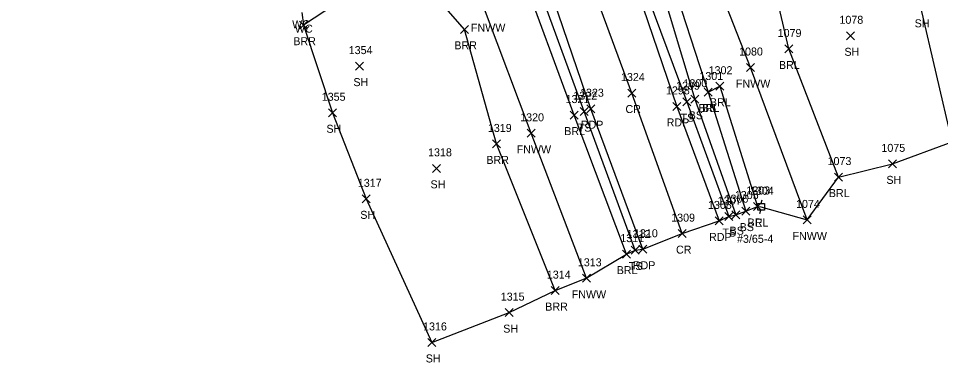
# Model space of a CAD drawing. Extents: x 1443590 to 1445966, y 578314 to 580556.
# Drawn here: x 1445262.8 to 1445493.3, y 578313.7 to 578399.7 of the extents above; entities that cross this region are included whole.
import ezdxf

# ---------------------------------------------------------------- set-up
doc = ezdxf.new("R2010")
doc.units = 0
for name, color, linetype in [('L_A', 7, 'Continuous'), ('L_I', 7, 'Continuous'), ('L_TIC', 7, 'Continuous'), ('LABL', 7, 'Continuous'), ('LELB', 7, 'Continuous'), ('LFNC', 7, 'Continuous'), ('LSOGP', 7, 'Continuous'), ('P_A', 7, 'Continuous'), ('P_I', 7, 'Continuous'), ('P_TIC', 7, 'Continuous'), ('PET', 7, 'Continuous'), ('PRC', 7, 'Continuous'), ('U_A', 7, 'Continuous'), ('U_C', 7, 'Continuous'), ('U_I', 7, 'Continuous'), ('UEPT', 7, 'Continuous')]:
    doc.layers.add(name, color=color, linetype=linetype)

msp = doc.modelspace()

# ---------------------------------------------------------------- linework, layer by layer
at = {"layer": 'L_TIC'}
for points in [[(1445333.02, 578397.02), (1445335.02, 578399.02)], [(1445335.02, 578397.02), (1445333.02, 578399.02)], [(1445373.28, 578395.98), (1445375.28, 578397.98)], [(1445375.28, 578395.98), (1445373.28, 578397.98)], [(1445469.81, 578394.37), (1445471.81, 578396.37)], [(1445471.81, 578394.37), (1445469.81, 578396.37)], [(1445454.38, 578391.07), (1445456.38, 578393.07)], [(1445456.38, 578391.07), (1445454.38, 578393.07)], [(1445347.05, 578386.79), (1445349.05, 578388.79)], [(1445349.05, 578386.79), (1445347.05, 578388.79)], [(1445444.8, 578386.44), (1445446.8, 578388.44)], [(1445446.8, 578386.44), (1445444.8, 578388.44)], [(1445437.11, 578381.76), (1445439.11, 578383.76)], [(1445439.11, 578381.76), (1445437.11, 578383.76)], [(1445430.91, 578378.51), (1445432.91, 578380.51)], [(1445432.91, 578378.51), (1445430.91, 578380.51)], [(1445434.24, 578380.31), (1445436.24, 578382.31)], [(1445436.24, 578380.31), (1445434.24, 578382.31)], [(1445434.24, 578380.31), (1445436.24, 578382.31)], [(1445436.24, 578380.31), (1445434.24, 578382.31)], [(1445428.91, 578377.9), (1445430.91, 578379.9)], [(1445430.91, 578377.9), (1445428.91, 578379.9)], [(1445340.32, 578375.13), (1445342.32, 578377.13)], [(1445342.32, 578375.13), (1445340.32, 578377.13)], [(1445400.7, 578374.55), (1445402.7, 578376.55)], [(1445402.7, 578374.55), (1445400.7, 578376.55)], [(1445403.21, 578375.42), (1445405.21, 578377.42)], [(1445405.21, 578375.42), (1445403.21, 578377.42)], [(1445390, 578369.99), (1445392, 578371.99)], [(1445392, 578369.99), (1445390, 578371.99)], [(1445381.28, 578367.34), (1445383.28, 578369.34)], [(1445383.28, 578367.34), (1445381.28, 578369.34)], [(1445480.3, 578362.36), (1445482.3, 578364.36)], [(1445482.3, 578362.36), (1445480.3, 578364.36)], [(1445366.33, 578361.24), (1445368.33, 578363.24)], [(1445368.33, 578361.24), (1445366.33, 578363.24)], [(1445466.84, 578359.06), (1445468.84, 578361.06)], [(1445468.84, 578359.06), (1445466.84, 578361.06)], [(1445348.76, 578353.62), (1445350.76, 578355.62)], [(1445350.76, 578353.62), (1445348.76, 578355.62)], [(1445446.54, 578351.71), (1445448.54, 578353.71)], [(1445448.54, 578351.71), (1445446.54, 578353.71)], [(1445439.4, 578349.18), (1445441.4, 578351.18)], [(1445441.4, 578349.18), (1445439.4, 578351.18)], [(1445441.14, 578349.66), (1445443.14, 578351.66)], [(1445443.14, 578349.66), (1445441.14, 578351.66)], [(1445443.66, 578350.56), (1445445.66, 578352.56)], [(1445445.66, 578350.56), (1445443.66, 578352.56)], [(1445458.96, 578348.35), (1445460.96, 578350.35)], [(1445460.96, 578348.35), (1445458.96, 578350.35)], [(1445413.81, 578339.8), (1445415.81, 578341.8)], [(1445415.81, 578339.8), (1445413.81, 578341.8)], [(1445415.98, 578340.83), (1445417.98, 578342.83)], [(1445417.98, 578340.83), (1445415.98, 578342.83)], [(1445403.77, 578333.76), (1445405.77, 578335.76)], [(1445405.77, 578333.76), (1445403.77, 578335.76)], [(1445396.01, 578330.68), (1445398.01, 578332.68)], [(1445398.01, 578330.68), (1445396.01, 578332.68)], [(1445384.5, 578325.18), (1445386.5, 578327.18)], [(1445386.5, 578325.18), (1445384.5, 578327.18)], [(1445365.13, 578317.73), (1445367.13, 578319.73)], [(1445367.13, 578317.73), (1445365.13, 578319.73)]]:
    msp.add_lwpolyline(points, dxfattribs=at)
at = {"layer": 'LABL'}
for points in [[(1445467.84, 578360.06), (1445455.38, 578392.07), (1445446.82, 578428.87), (1445442.38, 578441.48), (1445436.55, 578457.59), (1445425.34, 578488.87), (1445418.21, 578516.65), (1445402.21, 578560.94), (1445385.83, 578595.27), (1445371.99, 578640.68), (1445356.66, 578684.35), (1445342.86, 578722.22), (1445331.82, 578758.2), (1445312.95, 578811.34), (1445309.58, 578818.49), (1445306.72, 578822.66), (1445303.45, 578826.18), (1445294.95, 578830.16), (1445285.99, 578855.57), (1445278.07, 578895.34), (1445273.01, 578922.07), (1445267.74, 578942.65), (1445247.28, 578957.13)], [(1445292.63, 578789.9), (1445288, 578780.72), (1445303.45, 578740.92), (1445320.45, 578696.23), (1445336.45, 578651.8), (1445353.16, 578609.77), (1445368.17, 578573), (1445383.72, 578526.34), (1445398.46, 578486.57), (1445412.31, 578451.09), (1445415.12, 578445.83), (1445420.11, 578428.88), (1445425.31, 578411.87), (1445435.24, 578381.31), (1445438.11, 578382.76), (1445447.54, 578352.71)], [(1445414.81, 578340.8), (1445401.7, 578375.55), (1445388.17, 578412.4), (1445382.57, 578425.95), (1445377.8, 578432.04), (1445377.55, 578433.04), (1445376.34, 578435.51), (1445372.5, 578441.21), (1445366.97, 578466.65), (1445351.62, 578511.32), (1445336.85, 578548.71)], [(1445397.01, 578331.68), (1445382.28, 578368.34), (1445374.28, 578396.98), (1445358.31, 578415.37), (1445344.45, 578404.9), (1445334.02, 578398.02)]]:
    msp.add_lwpolyline(points, dxfattribs=at)
at = {"layer": 'LELB'}
for points in [[(1445222.69, 578937.93), (1445234.28, 578911.39), (1445254.78, 578861.13), (1445268.94, 578819.8), (1445281.41, 578785.26), (1445283.41, 578779.74), (1445299.6, 578739.58), (1445316.15, 578694.47), (1445332.79, 578650.27), (1445347.4, 578607.95), (1445361.62, 578570.36), (1445377.25, 578524), (1445391.22, 578483.59), (1445406.36, 578442.9), (1445418.34, 578410.04), (1445429.91, 578378.9), (1445440.4, 578350.18)], [(1445336.45, 578651.8), (1445350.45, 578608.68), (1445364.47, 578571.58), (1445379.66, 578524.91), (1445393.71, 578484.47), (1445409.17, 578449.94), (1445411.12, 578445.67), (1445411.54, 578444.09), (1445413.6, 578439.47), (1445415.72, 578428.29), (1445422.38, 578411.18), (1445431.91, 578379.51), (1445442.14, 578350.66)], [(1445416.98, 578341.83), (1445404.21, 578376.42), (1445390.71, 578413.34), (1445383.61, 578436.1), (1445371.7, 578468.44), (1445355.7, 578512.19), (1445341.33, 578550.44)], [(1445435.24, 578381.31), (1445444.66, 578351.56)]]:
    msp.add_lwpolyline(points, dxfattribs=at)
at = {"layer": 'LFNC'}
for points in [[(1445459.96, 578349.35), (1445445.8, 578387.44), (1445435.66, 578413.46), (1445430.43, 578428.44), (1445420.82, 578457.49), (1445411.95, 578480.76), (1445399.21, 578511.56), (1445382.81, 578556.03), (1445370.45, 578591.65), (1445354.37, 578635.55), (1445339.12, 578673.28), (1445323.48, 578719.9), (1445315.49, 578748.71)], [(1445404.77, 578334.76), (1445391, 578370.99), (1445379.57, 578401.39), (1445375.71, 578416.07)]]:
    msp.add_lwpolyline(points, dxfattribs=at)
at = {"layer": 'LSOGP'}
msp.add_lwpolyline([(1445333.6, 578401.15), (1445334.02, 578398.03), (1445341.32, 578376.13), (1445349.76, 578354.62), (1445366.13, 578318.74), (1445385.5, 578326.19), (1445397.01, 578331.68), (1445404.76, 578334.77), (1445414.81, 578340.8), (1445416.98, 578341.83), (1445418.89, 578342.02), (1445428.76, 578345.93), (1445437.94, 578349.11), (1445440.4, 578350.18), (1445442.14, 578350.66), (1445444.66, 578351.57), (1445447.54, 578352.71), (1445448.43, 578352.64), (1445459.96, 578349.35), (1445467.83, 578360.07), (1445481.3, 578363.36), (1445496.19, 578368.86), (1445488.35, 578402.49)], dxfattribs=at)
at = {"layer": 'P_TIC'}
for points in [[(1445415.12, 578380.06), (1445417.12, 578382.06)], [(1445417.12, 578380.06), (1445415.12, 578382.06)], [(1445426.35, 578376.72), (1445428.35, 578378.72)], [(1445428.35, 578376.72), (1445426.35, 578378.72)], [(1445404.88, 578376.14), (1445406.88, 578378.14)], [(1445406.88, 578376.14), (1445404.88, 578378.14)], [(1445436.94, 578348.1), (1445438.94, 578350.1)], [(1445438.94, 578348.1), (1445436.94, 578350.1)], [(1445427.76, 578344.92), (1445429.76, 578346.92)], [(1445429.76, 578344.92), (1445427.76, 578346.92)], [(1445417.89, 578341.02), (1445419.89, 578343.02)], [(1445419.89, 578341.02), (1445417.89, 578343.02)]]:
    msp.add_lwpolyline(points, dxfattribs=at)
at = {"layer": 'PET'}
for points in [[(1445418.89, 578342.02), (1445405.88, 578377.14), (1445393.26, 578414.23), (1445384.94, 578436.64), (1445373.41, 578468.96), (1445357.56, 578512.83), (1445344.62, 578550.03), (1445330.99, 578586.22), (1445323.64, 578606.66), (1445310.56, 578643.56), (1445297.05, 578680.63), (1445286.07, 578712.45), (1445276.51, 578732.61), (1445268.43, 578753.25), (1445256.91, 578785.04), (1445249.61, 578806.41), (1445230.56, 578857.31), (1445217.97, 578888.99), (1445200.05, 578931.7), (1445199.72, 578935.44), (1445193.89, 578943.66), (1445183.72, 578968.31), (1445171.41, 579000.64)], [(1445204.47, 578977.72), (1445211.07, 578960.69), (1445220.5, 578936.98), (1445230.76, 578910.15), (1445251.08, 578859.52), (1445265.4, 578819.79), (1445279.28, 578781.46), (1445295.62, 578738.27), (1445312.78, 578693.03), (1445329.09, 578649.05), (1445344.77, 578606.81), (1445359.16, 578569.06), (1445375.47, 578523.38), (1445389.92, 578483.27), (1445404.56, 578441.9), (1445416.57, 578409.56), (1445427.35, 578377.72), (1445437.94, 578349.1)]]:
    msp.add_lwpolyline(points, dxfattribs=at)
at = {"layer": 'PRC'}
msp.add_lwpolyline([(1445428.76, 578345.92), (1445416.12, 578381.06), (1445402.82, 578417.2), (1445394.53, 578440.03), (1445382.79, 578472.56), (1445367.55, 578515.78), (1445354.3, 578552.77), (1445340.07, 578591.68), (1445332.93, 578610.75), (1445320.05, 578646.79), (1445306.48, 578683.94), (1445294.78, 578715.83), (1445285.68, 578740.23), (1445278.69, 578759.19), (1445266.72, 578790.29), (1445259.42, 578810.95), (1445240.14, 578861.33), (1445228.56, 578891.21), (1445209.9, 578937.12), (1445195.27, 578973.7), (1445179.73, 579007.4), (1445167.09, 579032.9), (1445157.85, 579050.89), (1445142.74, 579080.19)], dxfattribs=at)
at = {"layer": 'UEPT'}
for p, q in [((1445447.6, 578351.8), (1445447.6, 578353.47)), ((1445447.6, 578353.47), (1445449.27, 578353.47)), ((1445448.6, 578354.3), (1445448.43, 578353.47)), ((1445449.27, 578353.47), (1445449.27, 578351.8)), ((1445449.27, 578351.8), (1445447.6, 578351.8)), ((1445448.18, 578350.97), (1445448.43, 578351.8)), ((1445448.43, 578352.63), (1445448.43, 578352.63))]:
    msp.add_line(p, q, dxfattribs=at)

# ---------------------------------------------------------------- texts
at = {"layer": 'L_A'}
for s, p in [('WC', (1445331.21, 578397.26)), ('SH', (1445486.84, 578397.49)), ('WC', (1445331.91, 578396.15)), ('FNWW', (1445375.91, 578396.39)), ('BRR', (1445331.51, 578393.02)), ('BRR', (1445371.77, 578391.98)), ('SH', (1445469.3, 578390.37)), ('BRL', (1445452.92, 578387.07)), ('SH', (1445346.54, 578382.79)), ('FNWW', (1445442.15, 578382.44)), ('BRL', (1445432.78, 578376.31)), ('BS', (1445433.68, 578376.31)), ('BRL', (1445435.65, 578377.76)), ('TS', (1445428.32, 578373.9)), ('BS', (1445430.35, 578374.51)), ('SH', (1445339.8, 578371.13)), ('BRL', (1445399.24, 578370.55)), ('TS', (1445402.62, 578371.42)), ('FNWW', (1445387.35, 578365.99)), ('BRR', (1445379.77, 578363.34)), ('SH', (1445479.78, 578358.36)), ('SH', (1445365.81, 578357.24)), ('BRL', (1445465.38, 578355.06)), ('SH', (1445348.25, 578349.62)), ('BS', (1445443.1, 578346.56)), ('BRL', (1445445.08, 578347.71)), ('TS', (1445438.81, 578345.18)), ('BS', (1445440.58, 578345.66)), ('FNWW', (1445456.31, 578344.35)), ('BRL', (1445412.36, 578335.8)), ('TS', (1445415.39, 578336.83)), ('FNWW', (1445401.11, 578329.76)), ('BRR', (1445394.5, 578326.68)), ('SH', (1445383.99, 578321.18)), ('SH', (1445364.62, 578313.73))]:
    msp.add_text(s, height=2, dxfattribs=at).set_placement(p)
at = {"layer": 'L_I'}
for s, p in [('1078', (1445468.04, 578398.37)), ('1079', (1445452.6, 578395.07)), ('1354', (1445345.36, 578390.79)), ('1080', (1445442.95, 578390.44)), ('1302', (1445435.34, 578385.76)), ('1301', (1445433.03, 578384.31)), ('1301', (1445433.03, 578384.31)), ('1299', (1445427.21, 578381.9)), ('1300', (1445429.05, 578382.51)), ('1355', (1445338.62, 578379.13)), ('1321', (1445399.57, 578378.55)), ('1322', (1445401.52, 578379.42)), ('1320', (1445388.23, 578373.99)), ('1319', (1445380.15, 578371.34)), ('1318', (1445365.2, 578365.24)), ('1075', (1445478.53, 578366.36)), ('1073', (1445465.07, 578363.06)), ('1317', (1445347.64, 578357.62)), ('1303', (1445444.77, 578355.71)), ('1307', (1445437.63, 578353.18)), ('1306', (1445439.32, 578353.66)), ('1305', (1445441.89, 578354.56)), ('1074', (1445457.19, 578352.35)), ('1312', (1445414.85, 578344.83)), ('1311', (1445413.25, 578343.8)), ('1313', (1445402.64, 578337.76)), ('1314', (1445394.89, 578334.68)), ('1315', (1445383.37, 578329.18)), ('1316', (1445363.95, 578321.73))]:
    msp.add_text(s, height=2, dxfattribs=at).set_placement(p)
at = {"layer": 'P_A'}
for s, p in [('CR', (1445414.55, 578376.06)), ('RDP', (1445403.37, 578372.14)), ('RDP', (1445424.84, 578372.72)), ('RDP', (1445435.43, 578344.1)), ('CR', (1445427.19, 578340.92)), ('RDP', (1445416.38, 578337.02))]:
    msp.add_text(s, height=2, dxfattribs=at).set_placement(p)
at = {"layer": 'P_I'}
for s, p in [('1324', (1445413.43, 578384.06)), ('1323', (1445403.19, 578380.14)), ('1298', (1445424.66, 578380.72)), ('1308', (1445435.17, 578352.1)), ('1309', (1445425.98, 578348.92)), ('1310', (1445416.68, 578345.02))]:
    msp.add_text(s, height=2, dxfattribs=at).set_placement(p)
at = {"layer": 'U_A'}
msp.add_text('EL', height=2, dxfattribs=at).set_placement((1445446.97, 578347.63))
at = {"layer": 'U_C'}
msp.add_text('#3/65-4', height=2, dxfattribs=at).set_placement((1445442.43, 578343.63))
at = {"layer": 'U_I'}
msp.add_text('1304', height=2, dxfattribs=at).set_placement((1445445.66, 578355.63))

doc.saveas('drawing.dxf')
